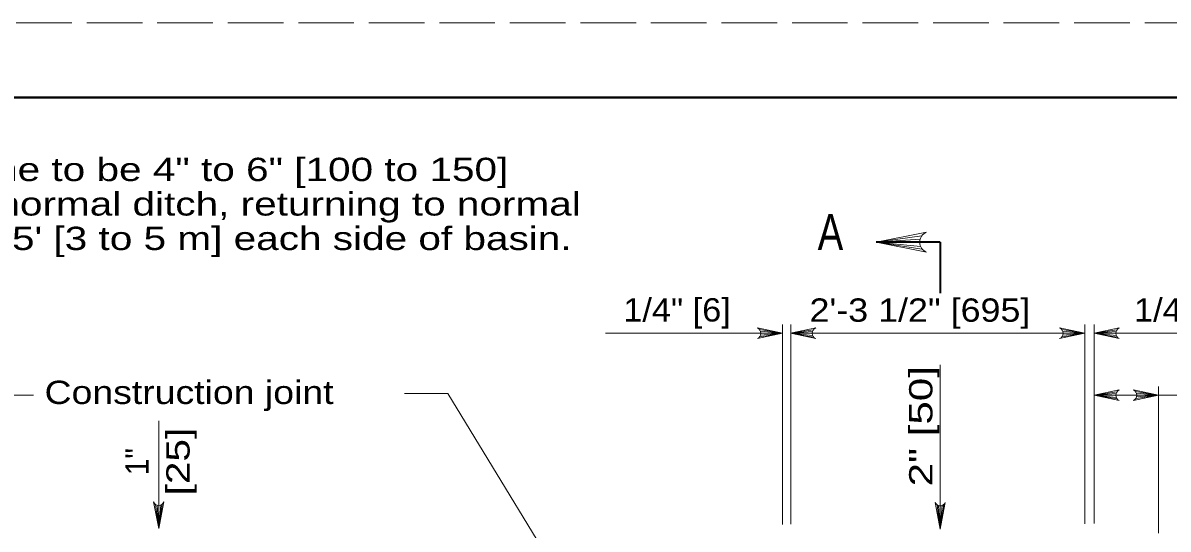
# Model space of a CAD drawing. Extents: x 1329.9 to 1363.9, y 715.5 to 737.5.
# Drawn here: x 1338.52 to 1346.18, y 734.11 to 737.5 of the extents above; entities that cross this region are included whole.
import ezdxf
from ezdxf.enums import TextEntityAlignment as Align

# ---------------------------------------------------------------- set-up
doc = ezdxf.new("R2010")
doc.units = 0
doc.header["$LTSCALE"] = 0.062
doc.linetypes.add('LONG_DASHED', pattern=[7.5, 6, -1.5])
doc.layers.add('1', color=7, linetype='Continuous', lineweight=13)

msp = doc.modelspace()

# ---------------------------------------------------------------- linework, layer by layer
at = {"layer": '1', "lineweight": 25}
msp.add_line((1331.86333, 736.9975), (1363.36333, 736.9975), dxfattribs=at)
at = {"layer": '1'}
for p, q in [((1344.53542, 736.07258), (1344.23083, 736.03)), ((1344.52508, 736.0515), (1344.23083, 736.03)), ((1344.522, 736.03), (1344.23083, 736.03)), ((1344.52733, 736.00258), (1344.23083, 736.03)), ((1344.539, 735.98292), (1344.23083, 736.03)), ((1342.41992, 735.42075), (1343.60433, 735.42075)), ((1343.45017, 735.44575), (1343.60425, 735.42075)), ((1343.452, 735.39825), (1343.60425, 735.42075)), ((1343.456, 735.43525), (1343.60425, 735.42075)), ((1343.45708, 735.40942), (1343.60425, 735.42075)), ((1343.45867, 735.42075), (1343.60425, 735.42075)), ((1343.60433, 734.14275), (1343.60433, 735.47933)), ((1343.8095, 735.44333), (1343.65717, 735.42075)), ((1343.80433, 735.43217), (1343.65717, 735.42075)), ((1343.80275, 735.42075), (1343.65717, 735.42075)), ((1343.8055, 735.40633), (1343.65717, 735.42075)), ((1343.81133, 735.39583), (1343.65717, 735.42075)), ((1343.658, 734.14308), (1343.658, 735.47933)), ((1343.658, 735.42075), (1345.62642, 735.42075)), ((1345.47233, 735.44575), (1345.62642, 735.42075)), ((1345.47408, 735.39825), (1345.62642, 735.42075)), ((1345.47817, 735.43525), (1345.62642, 735.42075)), ((1345.47925, 735.40942), (1345.62642, 735.42075)), ((1345.48083, 735.42075), (1345.62642, 735.42075)), ((1345.62642, 734.14692), (1345.62642, 735.47933)), ((1345.68883, 734.1475), (1345.68883, 735.47933)), ((1345.84117, 735.44333), (1345.68883, 735.42075)), ((1345.836, 735.43217), (1345.68883, 735.42075)), ((1345.68883, 735.42075), (1346.74308, 735.42075)), ((1345.83442, 735.42075), (1345.68883, 735.42075)), ((1345.83717, 735.40633), (1345.68883, 735.42075)), ((1345.843, 735.39583), (1345.68883, 735.42075)), ((1344.65908, 734.11167), (1344.65908, 735.21075)), ((1345.96608, 735.03167), (1346.12017, 735.00675)), ((1346.12017, 734.08408), (1346.12017, 735.06533)), ((1345.68883, 735.00675), (1347.29383, 735.00675)), ((1345.84133, 735.02917), (1345.68908, 735.00658)), ((1345.83617, 735.018), (1345.68908, 735.00658)), ((1345.83467, 735.00658), (1345.68908, 735.00658)), ((1345.83733, 734.99208), (1345.68908, 735.00658)), ((1345.84317, 734.98167), (1345.68908, 735.00658)), ((1345.96783, 734.98417), (1346.12017, 735.00675)), ((1345.97192, 735.02125), (1346.12017, 735.00675)), ((1345.973, 734.99533), (1346.12017, 735.00675)), ((1345.97458, 735.00675), (1346.12017, 735.00675)), ((1339.42875, 734.11492), (1339.42875, 734.83617)), ((1339.40742, 734.27617), (1339.42875, 734.11492)), ((1339.41792, 734.27075), (1339.42875, 734.11492)), ((1339.45225, 734.27808), (1339.42875, 734.11492)), ((1339.44242, 734.27192), (1339.42875, 734.11492)), ((1339.42875, 734.26908), (1339.42875, 734.11492)), ((1344.63783, 734.27292), (1344.65908, 734.11167)), ((1344.64833, 734.26742), (1344.65908, 734.11167)), ((1344.68267, 734.27475), (1344.65908, 734.11167)), ((1344.67275, 734.26858), (1344.65908, 734.11167)), ((1344.65908, 734.26575), (1344.65908, 734.11167))]:
    msp.add_line(p, q, dxfattribs=at)
at = {"layer": '1', "lineweight": 35}
for q in [(1344.23083, 736.03), (1344.65908, 735.68883)]:
    msp.add_line((1344.65908, 736.03), q, dxfattribs=at)
at = {"layer": '1', "linetype": 'LONG_DASHED'}
msp.add_lwpolyline([(1329.86333, 715.4975), (1363.86333, 715.4975), (1363.86333, 737.4975), (1329.86333, 737.4975)], close=True, dxfattribs=at)
at = {"layer": '1', "lineweight": 40}
msp.add_lwpolyline([(1331.86333, 736.9975), (1363.36333, 736.9975), (1363.36333, 715.9975), (1331.86333, 715.9975)], close=True, dxfattribs=at)
msp.add_lwpolyline([(1331.86333, 736.9975), (1363.36333, 736.9975), (1363.36333, 715.9975), (1331.86333, 715.9975)], close=True, dxfattribs=at)
at = {"layer": '1'}
for points in [[(1344.56725, 735.96267), (1344.23083, 736.03), (1344.56725, 736.09725)], [(1343.436, 735.45642), (1343.60425, 735.42075), (1343.436, 735.38517)], [(1343.82542, 735.38517), (1343.65717, 735.42075), (1343.82542, 735.45642)], [(1345.45817, 735.45642), (1345.62642, 735.42075), (1345.45817, 735.38517)], [(1345.85708, 735.38517), (1345.68883, 735.42075), (1345.85708, 735.45642)], [(1345.85725, 734.97092), (1345.68908, 735.00658), (1345.85725, 735.04217)], [(1345.95192, 735.04233), (1346.12017, 735.00675), (1345.95192, 734.97108)], [(1338.59067, 735.00633), (1338.312, 735.00633), (1337.42808, 733.47783)], [(1341.074, 735.0185), (1341.36325, 735.0185), (1342.28558, 733.50625)], [(1339.46233, 734.29308), (1339.42875, 734.11492), (1339.39508, 734.29308)], [(1344.69275, 734.28975), (1344.65908, 734.11167), (1344.6255, 734.28975)]]:
    msp.add_lwpolyline(points, dxfattribs=at)
msp.add_arc((1344.59445, 736.03005), 0.07261, 112.08782, 247.91395, dxfattribs=at)
for centre, major_axis, start_param, end_param in [((1343.42238, 735.42079), (0, -0.03844), 0.3855052, 2.7561184), ((1343.83907, 735.42079), (0, 0.03844), 0.3855052, 2.7561184), ((1345.44453, 735.42079), (0, -0.03844), 0.3855052, 2.7561184), ((1345.87075, 735.42079), (0, 0.03844), 0.3855052, 2.7561184), ((1345.87094, 735.00657), (0, 0.03844), 0.3855052, 2.7561184), ((1345.93828, 735.00673), (0, -0.03844), 0.3855052, 2.7561184), ((1339.42872, 734.3075), (0, -0.03844), 5.0978942, 7.4685073), ((1344.6591, 734.3042), (0, -0.03844), 5.0978942, 7.4685073)]:
    msp.add_ellipse(centre, major_axis=major_axis, ratio=0.944544, start_param=start_param, end_param=end_param, dxfattribs=at)

# ---------------------------------------------------------------- texts
for s, width, p in [('Flow line to be 4" to 6" [100 to 150]', 1.3, (1337.56558, 736.43942)), ('below normal ditch, returning to normal', 1.3, (1337.56558, 736.20867)), ("10' to 15' [3 to 5 m] each side of basin.", 1.3, (1337.56558, 735.97792)), ('2\'-3 1/2" [695]', 1.15, (1343.78408, 735.49825)), ('Construction joint', 1.2, (1338.66492, 734.94783))]:
    msp.add_text(s, height=0.156, dxfattribs=dict(at, width=width)).set_placement(p)
for s, height, width, p in [('A', 0.24, 0.8, (1343.92425, 735.97825)), ('1/4" [6]', 0.156, 1.1, (1342.89779, 735.49975)), ('1/4" [6]', 0.156, 1.1, (1346.31588, 735.49975))]:
    msp.add_text(s, height=height, dxfattribs=dict(at, width=width)).set_placement(p, align=Align.CENTER)
for s, width, p in [('2" [50]', 1.35, (1344.60675, 734.79929)), ('[25]', 1.3, (1339.63575, 734.56254)), ('1"', 0.95, (1339.36167, 734.56254))]:
    msp.add_text(s, height=0.156, rotation=90, dxfattribs=dict(at, width=width)).set_placement(p, align=Align.CENTER)

doc.saveas('drawing.dxf')
